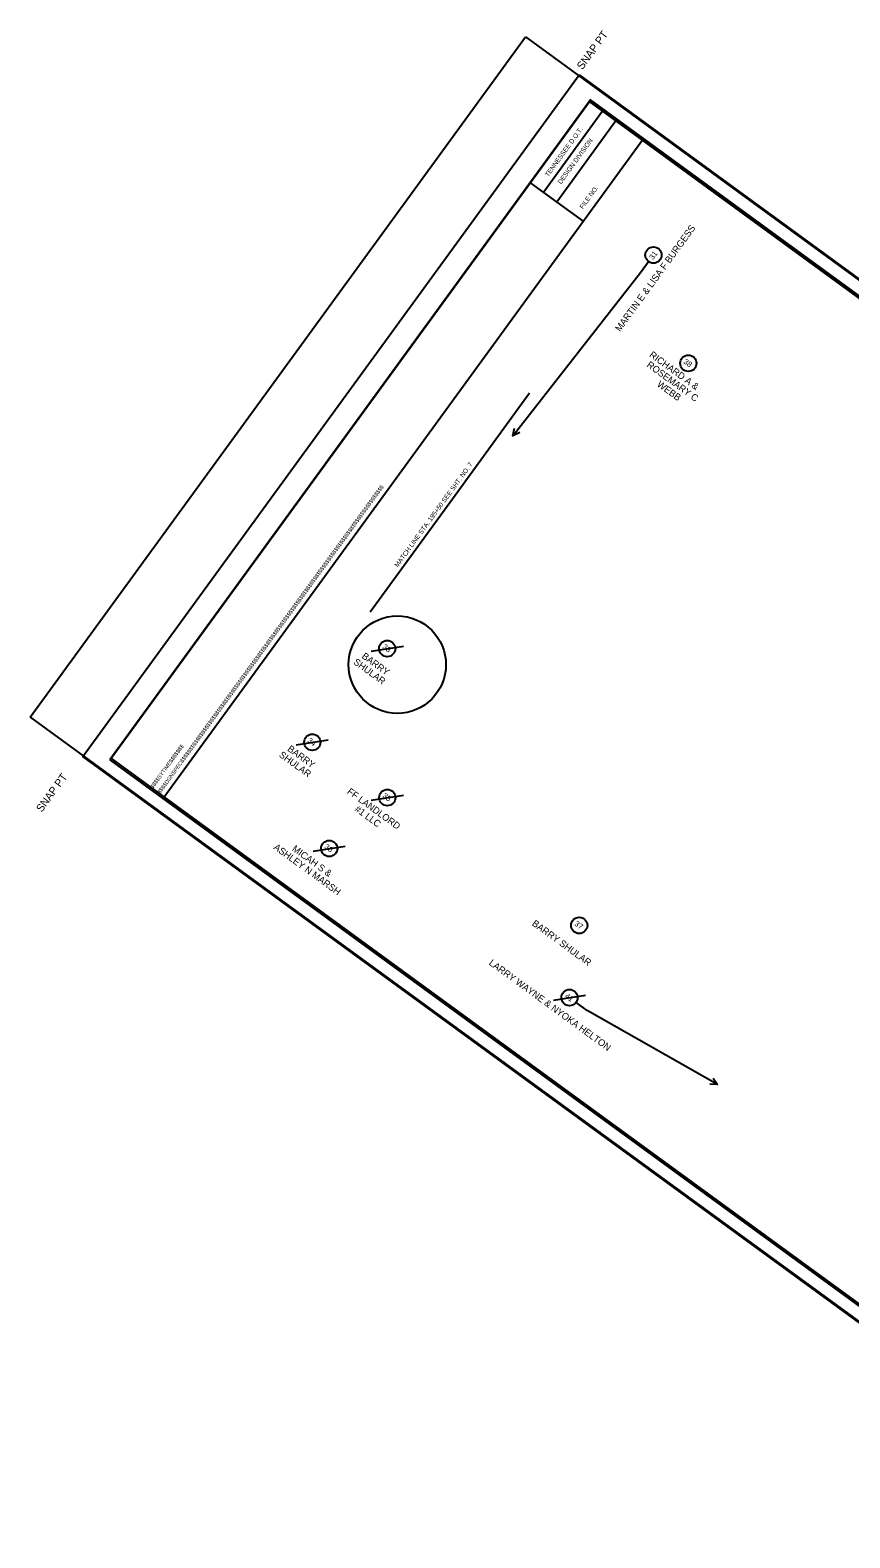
# Model space of a CAD drawing. Extents: x 2630958 to 2633078, y 566931 to 568943.
# Drawn here: x 2630958 to 2632018, y 566995 to 568943 of the extents above; entities that cross this region are included whole.
import ezdxf

# ---------------------------------------------------------------- set-up
doc = ezdxf.new("R2010")
doc.units = 0
for name, color, linetype in [('DESIGN - CENTERLINE - Proposed Text', 7, 'Continuous'), ('DESIGN - SCRATCH - User 1', 7, 'Continuous'), ('DESIGN - SHEET - Corner Text', 7, 'Continuous'), ('DESIGN - SHEET - Light Grid', 7, 'Continuous'), ('DESIGN - SHEET - Linework', 7, 'Continuous'), ('DESIGN - SHEET - Plot Shape', 7, 'Continuous'), ('SURVEY - PROPERTY - Owners', 7, 'Continuous'), ('SURVEY - PROPERTY - Tract Numbers', 7, 'Continuous')]:
    doc.layers.add(name, color=color, linetype=linetype)

msp = doc.modelspace()

# ---------------------------------------------------------------- linework, layer by layer
at = {"layer": 'DESIGN - CENTERLINE - Proposed Text'}
msp.add_lwpolyline([(2631397.5, 568191.1), (2631500.6, 568332.6), (2631603.6, 568474)], dxfattribs=at)
at = {"layer": 'DESIGN - SCRATCH - User 1'}
msp.add_line((2631481, 568346.8), (2631481, 568346.8), dxfattribs=at)
at = {"layer": 'DESIGN - SHEET - Corner Text'}
msp.add_circle((2631432.8, 568123), 62.9, dxfattribs=at)
at = {"layer": 'DESIGN - SHEET - Light Grid'}
msp.add_lwpolyline([(2631061.2, 568000), (2632406.8, 567019.4), (2633028.1, 567872.1), (2631682.5, 568852.7)], close=True, dxfattribs=at)
at = {"layer": 'DESIGN - SHEET - Linework'}
for p, q in [((2630958.1, 568055.1), (2631598.5, 568933.9)), ((2631598.5, 568933.9), (2633053.2, 567873.8)), ((2631698.2, 568838.1), (2631621.7, 568733.1)), ((2631715.5, 568825.6), (2631638.9, 568720.6)), ((2630958.1, 568055.1), (2632412.8, 566995))]:
    msp.add_line(p, q, dxfattribs=at)
for points in [[(2631749.8, 568800.5), (2631681.1, 568850.6), (2631604.6, 568745.6), (2631673.3, 568695.6)], [(2631749.8, 568800.5), (2631131.4, 567952), (2632403.6, 567024.8), (2633022, 567873.4), (2631749.8, 568800.5)]]:
    msp.add_lwpolyline(points, dxfattribs=at)
at = {"layer": 'DESIGN - SHEET - Plot Shape'}
for points in [[(2631667.7, 568884.8), (2633041.6, 567883.5), (2632400, 567003.1), (2631026.1, 568004.3)], [(2631681.1, 568850.6), (2633022, 567873.4), (2632403.6, 567024.8), (2631062.7, 568002)]]:
    msp.add_lwpolyline(points, close=True, dxfattribs=at)
at = {"layer": 'SURVEY - PROPERTY - Tract Numbers'}
for p, q in [((2631399.1, 568140.5), (2631440.6, 568147)), ((2631302.1, 568019.5), (2631343.6, 568026)), ((2631399.1, 567948.1), (2631440.6, 567954.6)), ((2631324.1, 567882.2), (2631365.6, 567888.7)), ((2631634.7, 567689.6), (2631676.2, 567696.1))]:
    msp.add_line(p, q, dxfattribs=at)
for points in [[(2631747.4, 568629.5), (2631757.7, 568643.7)], [(2631582.2, 568418.7), (2631747.4, 568629.5)], [(2631591.1, 568422.9), (2631582.2, 568418.7), (2631584.2, 568428.3)], [(2631678.1, 567676.4), (2631663.9, 567686.7)], [(2631846.7, 567580.6), (2631678.1, 567676.4)], [(2631841.2, 567588.7), (2631846.7, 567580.6), (2631836.9, 567581.1)]]:
    msp.add_lwpolyline(points, dxfattribs=at)
for centre in [(2631763.9, 568652.1), (2631809, 568512.3), (2631419.8, 568143.8), (2631322.9, 568022.8), (2631419.9, 567951.3), (2631344.8, 567885.5), (2631668, 567786.2), (2631655.4, 567692.9)]:
    msp.add_circle(centre, 10.5, dxfattribs=at)

# ---------------------------------------------------------------- texts
at = {"layer": 'DESIGN - CENTERLINE - Proposed Text'}
msp.add_text('MATCH LINE STA. 195+50 SEE SHT. NO. 7', height=6, rotation=53.918, dxfattribs=at).set_placement((2631433.5, 568248.2))
at = {"layer": 'DESIGN - SHEET - Corner Text'}
for s, height, p in [('  SNAP PT', 10, (2631667.7, 568884.8)), ('TENNESSEE D.O.T.', 6, (2631628, 568752.7)), ('DESIGN DIVISION', 6, (2631644.5, 568743.2)), ('FILE NO.', 6, (2631672.7, 568711)), ('$$$$DGNSPEC$$$$$$$$$$$$$$$$$$$$$$$$$$$$$$$$$$$$$$$$$$$$$$$$$$$$$$$$$$$$$$$$$$$$$$$$$$$$$$$$$$$$$$$$$$$$$$$$$$$$$$$$$$$$$$$$$$$', 5.0001, (2631126.3, 567955.7)), ('$$$$SYTIME$$$$$$$', 5, (2631116.9, 567962.5)), ('SNAP PT  ', 10, (2630973.1, 567931.6))]:
    msp.add_text(s, height=height, rotation=53.918, dxfattribs=at).set_placement(p)
at = {"layer": 'SURVEY - PROPERTY - Owners'}
for s, rotation, p in [('MARTIN E & LISA F BURGESS', 53.918, (2631720.7, 568552.5)), ('ROSEMARY C', 323.918, (2631754.4, 568508.6)), ('RICHARD A &', 323.918, (2631757.8, 568521.5)), ('WEBB', 323.918, (2631767.7, 568483.4)), ('SHULAR', 323.918, (2631375.2, 568124.7)), ('BARRY', 323.918, (2631386, 568132.3)), ('SHULAR', 323.918, (2631279.1, 568004.8)), ('BARRY', 323.918, (2631289.9, 568012.5)), ('FF LANDLORD', 323.918, (2631367.1, 567957.3)), ('#1 LLC', 323.918, (2631377, 567934.6)), ('ASHLEY N MARSH', 323.918, (2631272.1, 567885.4)), ('MICAH S &', 323.918, (2631296, 567883.4)), ('BARRY SHULAR', 323.918, (2631606.1, 567786.9)), ('LARRY WAYNE & NYOKA HELTON', 323.918, (2631550.4, 567736))]:
    msp.add_text(s, height=8.75, rotation=rotation, dxfattribs=at).set_placement(p)
at = {"layer": 'SURVEY - PROPERTY - Tract Numbers'}
for s, rotation, p in [('31', 53.918, (2631763.4, 568645.4)), ('38', 323.918, (2631802, 568513)), ('33', 323.918, (2631412.9, 568144.5)), ('34', 323.918, (2631315.9, 568023.5)), ('35', 323.918, (2631413, 567952.1)), ('36', 323.918, (2631337.8, 567886.3)), ('37', 323.918, (2631661.1, 567786.9)), ('41', 323.918, (2631648.7, 567693.4))]:
    msp.add_text(s, height=7, rotation=rotation, dxfattribs=at).set_placement(p)

doc.saveas('drawing.dxf')
